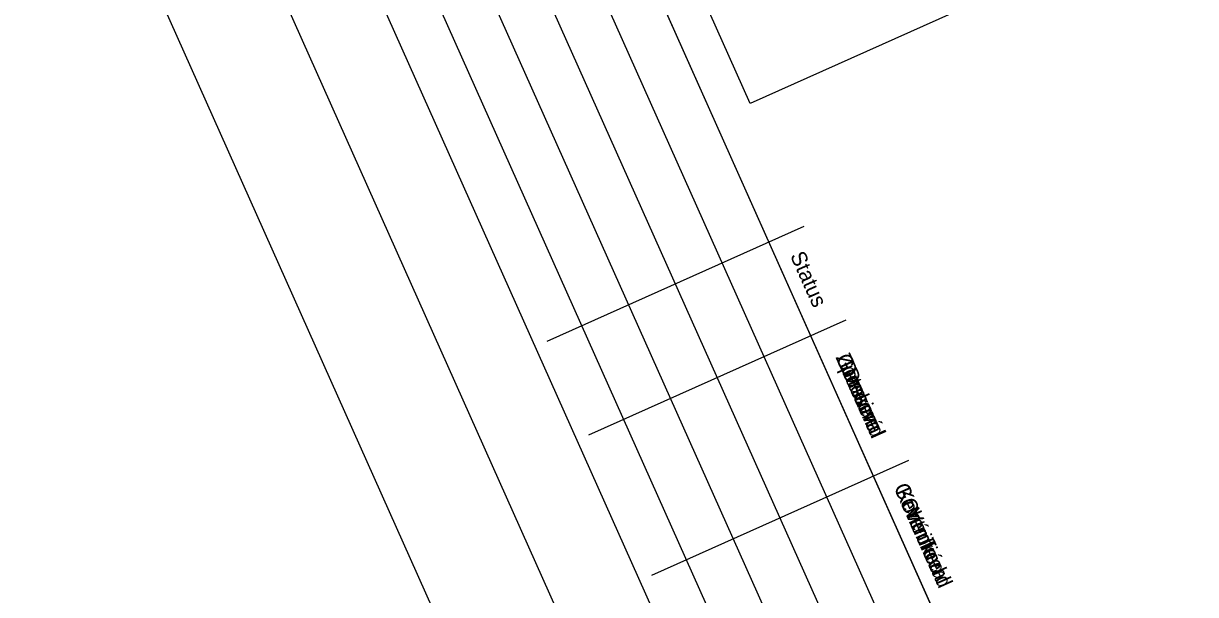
# Model space of a CAD drawing. Extents: x -781656 to -760591, y -1008106 to -975620.
# Drawn here: x -781651.438 to -781649.149, y -1008103.54 to -1008102.426 of the extents above; entities that cross this region are included whole.
import ezdxf

# ---------------------------------------------------------------- set-up
doc = ezdxf.new("R2010")
doc.units = 0
for name, color, linetype in [('Border', 7, 'Continuous'), ('Border_TextCZ', 7, 'Continuous'), ('Border_TextFR', 7, 'Continuous'), ('Border_TextNL', 7, 'Continuous'), ('Border_TextUK', 7, 'Continuous'), ('SL_05_KOMUNIKACE', 7, 'Continuous')]:
    doc.layers.add(name, color=color, linetype=linetype)

# ---------------------------------------------------------------- blocks, each defined once
blk = doc.blocks.new('A3coversheet_v03_CZ_1_1')
at = {"layer": 'Border'}
blk.add_line((2.1958, 1.5206), (4.0958, 1.5206), dxfattribs=at)
for points in [[(3.4042, 1.5581), (3.4042, 1.2831)], [(3.5042, 1.5581), (3.5042, 1.2831)], [(3.6542, 1.5581), (3.6542, 1.2831)], [(2.1958, 1.5206), (4.1042, 1.5206)], [(2.1958, 1.4706), (4.1042, 1.4706)], [(2.1958, 1.4206), (4.1042, 1.4206)], [(2.1958, 1.3706), (4.1042, 1.3706)], [(2.1958, 1.3206), (4.1042, 1.3206)], [(2.1958, 1.2706), (4.1042, 1.2706)], [(2.1958, 1.185), (4.1042, 1.185)], [(2.1958, 1.075), (4.1042, 1.075)]]:
    blk.add_lwpolyline(points, dxfattribs=at)
at = {"layer": 'Border_TextCZ'}
for s, p in [('Status', (3.4245, 1.534)), ('Zpracoval', (3.5332, 1.534)), ('Kontroloval', (3.6768, 1.534))]:
    blk.add_text(s, height=0.015, dxfattribs=at).set_placement(p)
at = {"layer": 'Border_TextFR'}
for s, p in [('Status', (3.4245, 1.534)), ('Dessiné', (3.5413, 1.534)), ('Vérifié', (3.6995, 1.534))]:
    blk.add_text(s, height=0.015, dxfattribs=at).set_placement(p)
at = {"layer": 'Border_TextNL'}
for s, p in [('Status', (3.4245, 1.534)), ('Getekend', (3.5337, 1.534)), ('Geverifieerd', (3.6721, 1.534))]:
    blk.add_text(s, height=0.015, dxfattribs=at).set_placement(p)
at = {"layer": 'Border_TextUK'}
for s, p in [('Status', (3.4245, 1.534)), ('Drawn', (3.5489, 1.534)), ('Checked', (3.6878, 1.534))]:
    blk.add_text(s, height=0.015, dxfattribs=at).set_placement(p)
blk = doc.blocks.new('přehledka_1')
at = {"layer": 'Border'}
blk.add_lwpolyline([(0, 0), (0.9992, 0), (0.9992, -0.6522), (0, -0.6522)], close=True, dxfattribs=at)

msp = doc.modelspace()

# ---------------------------------------------------------------- block references
at = {"layer": 'Border', "xscale": 2.0000000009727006, "yscale": 2.0000000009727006, "rotation": -65.8996989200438}
msp.add_blockref('A3coversheet_v03_CZ_1_1', (-781655.5387, -1008097.8791), dxfattribs=at)
at = {"layer": 'SL_05_KOMUNIKACE', "xscale": 1.999998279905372, "yscale": 1.999998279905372, "rotation": -65.89969891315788}
msp.add_blockref('přehledka_1', (-781649.644, -1008100.2249), dxfattribs=at)

doc.saveas('drawing.dxf')
